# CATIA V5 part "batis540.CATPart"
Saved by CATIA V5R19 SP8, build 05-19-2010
Part number: bati
Bounding box of the stored display mesh (mm): x -20 to 20, y -125 to 125, z -25 to 200
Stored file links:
  F:\projetcatiafinal\0540-VIGUIER\CAO\batis540.CATPart
  F:\projetcatiafinal\0540-VIGUIER\CAO\0540.CATProduct
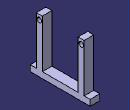
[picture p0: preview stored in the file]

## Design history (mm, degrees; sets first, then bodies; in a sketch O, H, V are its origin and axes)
Parameters
  rayon_assemblage = 10 mm
External parameters (linked from other documents)
  External.longueur_bielles = 200 mm
AxisSystem1: origin (0, 0, 0), X (1, 0, 0), Y (0, 1, 0), Z (0, 0, 1)
Body1 (main body)
  Sketch1 on YZ plane of AxisSystem1, origin (0, 0, 0), H (0, 1, 0), V (0, 0, 1)
    reference intersected line E1 through (0, 0) direction (0, 1) from ZX plane of AxisSystem1
    point P3 (0, 0)
    line L1 (-125, -25) -> (-125, 0)
    point P5 (-125, 0)
    line L2 (-125, 0) -> (-100, 0)
    line L3 (-100, 0) -> (-100, 200)
    line L4 (-100, 200) -> (-75, 200)
    line L5 (-75, 200) -> (-75, 0)
    point P9 (-75, 0)
    line L6 (-75, 0) -> (75, 0)
    line L7 (75, 0) -> (75, 200)
    point P11 (75, 200)
    line L8 (75, 200) -> (100, 200)
    line L9 (100, 200) -> (100, 0)
    point P13 (100, 0)
    line L10 (100, 0) -> (125, 0)
    line L11 (125, 0) -> (125, -25)
    line L12 (125, -25) -> (-125, -25)
    length L12 = 250 {= External.longueur_bielles +(External.longueur_bielles /4)}
    length L1 = 25
    distance L4 L6 = 200 {= External.longueur_bielles}
    distance L3 L9 = 200 {= External.longueur_bielles}
    distance L3 L5 = 25 {= 2*rayon_assemblage +(0.5*rayon_assemblage )}
    coincidence: P5 H, P9 H, P11 L4, P13 H
    vertical: L1 V, L3 V, L5 V, L7 V, L9 V, L11 V
    horizontal: L2 H, L4 H, L6 H, L8 H, L10 H, L12 H
    symmetry: L9 L3 E1, L11 L1 E1, L5 L7 E1
  Pad1: profile Sketch1, direction (1, 0, 0), length 20, mirrored extent
  Sketch2 on end face of Pad1, origin (20, 0, 0), H (0, 1, 0), V (0, 0, 1)
    circle A1 centre (-87.5, 180) radius 10
    point P1 (-87.5, 180)
    circle A2 centre (87.5, 180) radius 10
    point P2 (87.5, 180)
    reference projected line E1 (-100, 200) -> (-100, 0) from edge [face of Pad1 from Sketch1.L3 | end face of Pad1]
    reference projected line E2 (-75, 0) -> (-75, 200) from edge [face of Pad1 from Sketch1.L5 | end face of Pad1]
    reference projected line E3 (100, 0) -> (100, 200) from edge [face of Pad1 from Sketch1.L9 | end face of Pad1]
    reference projected line E4 (75, 200) -> (75, 0) from edge [face of Pad1 from Sketch1.L7 | end face of Pad1]
    radius A2 = 10 {= rayon_assemblage}
    radius A1 = 10 {= rayon_assemblage}
    distance P2 H = 180 {= External.longueur_bielles -2*rayon_assemblage}
    distance P1 H = 180 {= External.longueur_bielles -2*rayon_assemblage}
    equidistance: E1 E2 P1, E3 E4 P2
  Pocket1: profile Sketch2, direction (-1, 0, 0), through (limit type 3)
